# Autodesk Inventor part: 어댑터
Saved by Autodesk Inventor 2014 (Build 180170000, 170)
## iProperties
Created: 2025-09
Part Number: 어댑터
Material: 일반
Document SubType Name: Modeling
Designer: dg
Density: 1 g/cm^3
Appearance: 기본값
Author: dg
Author: jhkim
Creation Date: 2025-09-02
Sending System: Autodesk Inventor 2026
Preprocessor: ST-DEVELOPER v20.1
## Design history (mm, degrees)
node "어댑터1"
node "솔리드1"
node "기준1"
